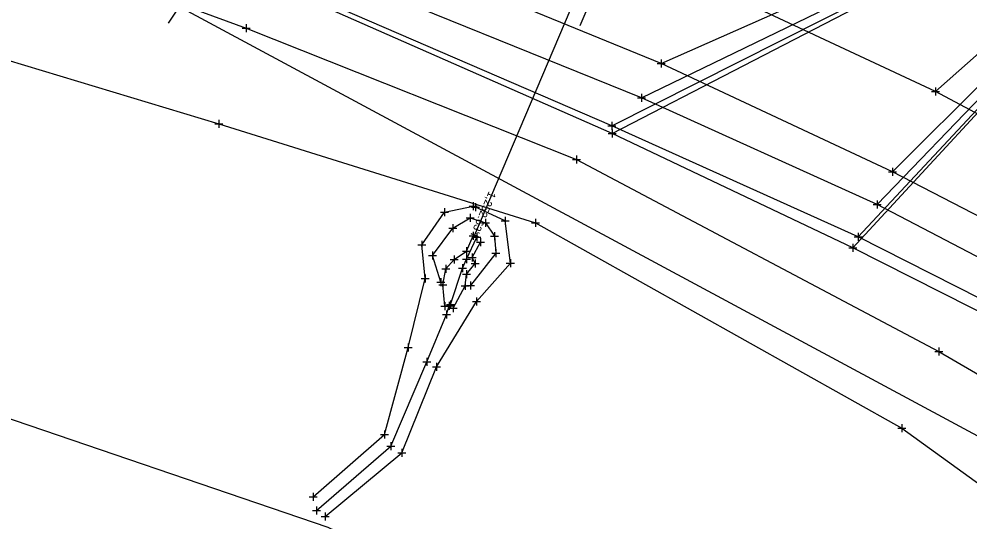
# Model space of a CAD drawing. Extents: x 125846 to 128609, y 511011 to 513388.
# Drawn here: x 126111.9 to 126230.6, y 513200.2 to 513263 of the extents above; entities that cross this region are included whole.
import ezdxf

# ---------------------------------------------------------------- set-up
doc = ezdxf.new("R2010")
doc.units = 0
for name, color, linetype in [('DR_X_Ditch', 7, 'Continuous'), ('DR_X_Elev_Flow', 7, 'Continuous'), ('DR_X_Storm_Sewer', 7, 'Continuous'), ('DR_X_Text', 7, 'Continuous'), ('DT_X_Terrain_Boundary', 7, 'Continuous'), ('PM_X_CL_Double_Solid', 7, 'Continuous'), ('PM_X_Edge_Line', 7, 'Continuous'), ('PV_X_COP', 7, 'Continuous'), ('PV_X_EOP', 7, 'Continuous'), ('PV_X_Shoulder_Aggregate', 7, 'Continuous'), ('RD_X_GR_Lt', 7, 'Continuous'), ('SC_Scratch1', 7, 'Continuous'), ('SV_Observation', 7, 'Continuous'), ('SV_X_Break_Lines', 7, 'Continuous'), ('UT_X_Overhead_Cable_TV', 7, 'Continuous'), ('UT_X_Overhead_Electric', 7, 'Continuous'), ('UT_X_Sanitary_Line', 7, 'Continuous')]:
    doc.layers.add(name, color=color, linetype=linetype)

msp = doc.modelspace()

# ---------------------------------------------------------------- linework, layer by layer
at = {"layer": 'DR_X_Ditch'}
for points in [[(126165.09, 513227.16), (126164.81, 513229.85), (126165.19, 513231.85), (126166.23, 513232.99), (126167.78, 513234.05), (126168.63, 513235.94)], [(126166.1, 513226.94), (126167.6, 513229.72), (126167.77, 513231.18), (126168.86, 513232.49), (126168.51, 513233.26), (126169.52, 513235.18)], [(126149.02, 513201.65), (126158.34, 513209.69), (126162.81, 513220.23), (126165.29, 513226.13), (126165.6, 513227.21)]]:
    msp.add_lwpolyline(points, dxfattribs=at)
at = {"layer": 'DR_X_Elev_Flow'}
for p, q in [((126168.32, 513236.26), (126169.25, 513235.87)), ((126168.98, 513236.53), (126168.59, 513235.6)), ((126168.79, 513236.06), (126168.79, 513236.06))]:
    msp.add_line(p, q, dxfattribs=at)
at = {"layer": 'DR_X_Storm_Sewer'}
msp.add_line((126200.85, 513311.44), (126168.79, 513236.06), dxfattribs=at)
at = {"layer": 'DR_X_Text'}
msp.add_line((126181.97, 513262.21), (126189.59, 513280.13), dxfattribs=at)
at = {"layer": 'DT_X_Terrain_Boundary'}
msp.add_line((126133.91, 513267.69), (126130.49, 513262.51), dxfattribs=at)
at = {"layer": 'PM_X_CL_Double_Solid'}
msp.add_lwpolyline([(126636.02, 512759.4), (126615.05, 512794.2), (126593.25, 512831.82), (126573.13, 512865.78), (126548.62, 512907.97), (126527.48, 512943.53), (126502.23, 512985.51), (126481.23, 513018.85), (126459.49, 513051.36), (126435.34, 513083.61), (126410.1, 513114.17), (126382.09, 513143.77), (126354.34, 513170.58), (126324.59, 513194.52), (126296.41, 513214.57), (126261.19, 513235.43), (126226.4, 513253.99), (126196.16, 513268.13), (126155.65, 513284.48), (126122.95, 513296.87), (126084.02, 513309.98), (126040.97, 513324.81)], dxfattribs=at)
at = {"layer": 'PM_X_Edge_Line'}
msp.add_lwpolyline([(126641.9, 512726.19), (126625.34, 512754.34), (126605.08, 512788.94), (126583.36, 512826.69), (126563.04, 512860.47), (126538.92, 512902.03), (126518.32, 512936.12), (126492.37, 512979.06), (126471.35, 513012.5), (126449.88, 513044.72), (126425.49, 513077.8), (126401.14, 513107.45), (126374.19, 513136.08), (126346.62, 513162.23), (126316.54, 513186.44), (126289.7, 513205.32), (126254.95, 513226.42), (126221.02, 513243.96), (126192.1, 513257.47), (126151.32, 513274.16), (126119.39, 513285.85), (126084.84, 513297.83), (126036.98, 513314.19)], dxfattribs=at)
at = {"layer": 'PV_X_COP'}
msp.add_lwpolyline([(126636.02, 512759.4), (126615.05, 512794.2), (126593.25, 512831.82), (126573.13, 512865.78), (126548.62, 512907.97), (126527.48, 512943.53), (126502.23, 512985.51), (126481.23, 513018.85), (126459.49, 513051.36), (126435.34, 513083.61), (126410.1, 513114.17), (126382.09, 513143.77), (126354.34, 513170.58), (126324.59, 513194.52), (126296.41, 513214.57), (126261.19, 513235.43), (126226.4, 513253.99), (126196.16, 513268.13), (126155.65, 513284.48), (126122.95, 513296.87), (126084.02, 513309.98), (126040.97, 513324.81)], dxfattribs=at)
at = {"layer": 'PV_X_EOP'}
msp.add_lwpolyline([(126637.98, 512724.06), (126621.53, 512752.01), (126602.03, 512784.44), (126578.51, 512824.31), (126558.07, 512859.52), (126534.26, 512899.49), (126514.02, 512933.73), (126488.13, 512977.21), (126467.93, 513009.24), (126445.31, 513042.52), (126421.52, 513074.55), (126397.03, 513104.15), (126370.98, 513132.02), (126342.57, 513158.56), (126313.71, 513182.07), (126286.69, 513201.08), (126252.27, 513222.55), (126219.11, 513239.86), (126189.65, 513253.2), (126149.87, 513269.3), (126117, 513281.26), (126083.11, 513293.41), (126035.31, 513309.49)], dxfattribs=at)
at = {"layer": 'PV_X_Shoulder_Aggregate'}
msp.add_lwpolyline([(126633.73, 512721.34), (126617.93, 512747.83), (126597.86, 512781.29), (126573.04, 512822.36), (126553.24, 512856.32), (126529.12, 512897.19), (126509.18, 512930.83), (126483.18, 512974.01), (126464.03, 513005.56), (126440.77, 513039.49), (126417.25, 513071.53), (126392.91, 513100.9), (126367.39, 513127.29), (126339.96, 513154.19), (126309.91, 513178.35), (126284.4, 513196.29), (126249.43, 513217.59), (126216.07, 513234.45), (126185.97, 513248.75), (126148.5, 513265.21), (126114.74, 513277.88), (126082.21, 513289.55), (126033.87, 513305.23)], dxfattribs=at)
at = {"layer": 'RD_X_GR_Lt'}
msp.add_lwpolyline([(126634.88, 512722.09), (126619.21, 512748.78), (126598.9, 512782.21), (126574.93, 512822.94), (126554.61, 512857.11), (126530.54, 512897.76), (126510.25, 512931.79), (126484.51, 512975.03), (126464.6, 513006.58), (126442.12, 513040.34), (126418.42, 513072.38), (126393.86, 513101.97), (126367.84, 513128.84), (126340.29, 513155.37), (126310.98, 513178.92), (126284.67, 513197.83), (126250.35, 513218.8), (126216.71, 513235.84), (126185.96, 513249.69), (126148.63, 513265.85), (126115.89, 513278.62), (126082.39, 513290.6), (126034.53, 513306.5)], dxfattribs=at)
at = {"layer": 'SV_Observation'}
for p in [(126185.96, 513249.69), (126185.97, 513248.75), (126189.65, 513253.2), (126192.1, 513257.47), (126216.07, 513234.45), (126216.71, 513235.84), (126219.11, 513239.86), (126221.02, 513243.96), (126226.4, 513253.99), (126226.4, 513253.99)]:
    msp.add_line(p, (126268.6, 513291.36), dxfattribs=at)
at = {"layer": 'SV_X_Break_Lines'}
for points in [[(125946.44, 513329.01), (126006.88, 513306.37), (126050.24, 513295.42), (126104.19, 513275.13), (126140.27, 513261.88), (126181.51, 513245.48), (126226.81, 513221.51), (126268.34, 513197.39), (126318.54, 513162.11), (126344.35, 513136.62), (126353.66, 513127.02)], [(125947.37, 513316.82), (126001.11, 513295.8), (126045.04, 513284.34), (126099.25, 513261.26), (126136.85, 513249.95), (126176.42, 513237.57), (126222.16, 513211.96), (126260.77, 513184.08), (126309.68, 513145.05), (126320.88, 513131.94), (126329.73, 513119.29)], [(126929.12, 511999.3), (126903.84, 512110.39), (126871.86, 512233.61), (126833.09, 512269.75), (126730.01, 512369.5), (126679.2, 512443.95), (126610.71, 512557), (126575.33, 512586.13), (126534.96, 512653.66), (126509.99, 512711.61), (126473.57, 512790.72), (126439.57, 512852.97), (126379.8, 512929.28), (126333.79, 513016.36), (126275.48, 513095.64), (126210.09, 513171.16), (126150.48, 513199.56), (126106, 513214.69), (126034.78, 513236.32), (125916.78, 513276.5), (125860.26, 513285.89)], [(126148.63, 513203.37), (126157.54, 513211.15), (126160.48, 513222), (126162.63, 513230.65), (126162.21, 513234.82), (126165.05, 513238.93), (126168.63, 513239.65)], [(126150.14, 513200.91), (126159.72, 513208.87), (126164.04, 513219.6), (126169.03, 513227.77), (126173.26, 513232.54), (126172.6, 513237.84), (126168.91, 513239.52)], [(126164.57, 513230.17), (126163.55, 513233.52), (126166.08, 513236.91), (126168.25, 513238.2), (126170.15, 513237.59), (126171.27, 513235.9), (126171.46, 513233.8), (126168.29, 513229.74)], [(126165.79, 513227.4), (126167.27, 513231.93), (126167.77, 513233.04), (126169.07, 513235.79)]]:
    msp.add_lwpolyline(points, dxfattribs=at)
at = {"layer": 'UT_X_Overhead_Cable_TV'}
msp.add_lwpolyline([(127118.02, 511376.72), (127063.55, 511579.79), (127023.04, 511824.95), (126985.21, 512054.96), (126933.25, 512195.56), (126884.63, 512286.17), (126796.71, 512439.39), (126673.51, 512645.42), (126573.76, 512808.4), (126463.86, 512978.44), (126309.69, 513169.01), (126131.86, 513264.58), (125938.03, 513331.21)], dxfattribs=at)
at = {"layer": 'UT_X_Overhead_Electric'}
msp.add_lwpolyline([(127118.02, 511376.72), (127063.55, 511579.79), (127023.04, 511824.95), (126985.21, 512054.96), (126933.25, 512195.56), (126884.63, 512286.17), (126796.71, 512439.39), (126673.51, 512645.42), (126573.76, 512808.4), (126463.86, 512978.44), (126309.69, 513169.01), (126131.86, 513264.58), (125938.03, 513331.21)], dxfattribs=at)
at = {"layer": 'UT_X_Sanitary_Line'}
for p, q in [((126139.77, 513261.88), (126140.77, 513261.88)), ((126140.27, 513262.38), (126140.27, 513261.38)), ((126140.27, 513261.88), (126140.27, 513261.88)), ((126191.6, 513257.47), (126192.6, 513257.47)), ((126192.1, 513257.97), (126192.1, 513256.97)), ((126192.1, 513257.47), (126192.1, 513257.47)), ((126189.65, 513253.7), (126189.65, 513252.7)), ((126225.9, 513253.99), (126226.9, 513253.99)), ((126225.9, 513253.99), (126226.9, 513253.99)), ((126226.4, 513254.49), (126226.4, 513253.49)), ((126226.4, 513254.49), (126226.4, 513253.49)), ((126226.4, 513253.99), (126226.4, 513253.99)), ((126226.4, 513253.99), (126226.4, 513253.99)), ((126189.15, 513253.2), (126190.15, 513253.2)), ((126189.65, 513253.2), (126189.65, 513253.2)), ((126136.35, 513249.95), (126137.35, 513249.95)), ((126136.85, 513250.45), (126136.85, 513249.45)), ((126136.85, 513249.95), (126136.85, 513249.95)), ((126185.96, 513250.19), (126185.96, 513249.19)), ((126185.46, 513249.69), (126186.46, 513249.69)), ((126185.47, 513248.75), (126186.47, 513248.75)), ((126185.96, 513249.69), (126185.96, 513249.69)), ((126185.97, 513249.25), (126185.97, 513248.25)), ((126185.97, 513248.75), (126185.97, 513248.75)), ((126181.01, 513245.48), (126182.01, 513245.48)), ((126181.51, 513245.98), (126181.51, 513244.98)), ((126181.51, 513245.48), (126181.51, 513245.48)), ((126221.02, 513244.46), (126221.02, 513243.46)), ((126220.52, 513243.96), (126221.52, 513243.96)), ((126221.02, 513243.96), (126221.02, 513243.96)), ((126165.05, 513239.43), (126165.05, 513238.43)), ((126168.13, 513239.65), (126169.13, 513239.65)), ((126168.41, 513239.52), (126169.41, 513239.52)), ((126168.63, 513240.15), (126168.63, 513239.15)), ((126168.63, 513239.65), (126168.63, 513239.65)), ((126168.91, 513240.02), (126168.91, 513239.02)), ((126168.91, 513239.52), (126168.91, 513239.52)), ((126218.61, 513239.86), (126219.61, 513239.86)), ((126219.11, 513240.36), (126219.11, 513239.36)), ((126219.11, 513239.86), (126219.11, 513239.86)), ((126164.55, 513238.93), (126165.55, 513238.93)), ((126165.05, 513238.93), (126165.05, 513238.93)), ((126167.75, 513238.2), (126168.75, 513238.2)), ((126168.25, 513238.7), (126168.25, 513237.7)), ((126168.25, 513238.2), (126168.25, 513238.2)), ((126170.15, 513238.09), (126170.15, 513237.09)), ((126172.6, 513238.34), (126172.6, 513237.34)), ((126176.42, 513238.07), (126176.42, 513237.07)), ((126165.58, 513236.91), (126166.58, 513236.91)), ((126166.08, 513237.41), (126166.08, 513236.41)), ((126166.08, 513236.91), (126166.08, 513236.91)), ((126169.65, 513237.59), (126170.65, 513237.59)), ((126170.15, 513237.59), (126170.15, 513237.59)), ((126172.1, 513237.84), (126173.1, 513237.84)), ((126172.6, 513237.84), (126172.6, 513237.84)), ((126175.92, 513237.57), (126176.92, 513237.57)), ((126176.42, 513237.57), (126176.42, 513237.57)), ((126168.13, 513235.94), (126169.13, 513235.94)), ((126168.57, 513235.79), (126169.57, 513235.79)), ((126168.63, 513236.44), (126168.63, 513235.44)), ((126168.63, 513235.94), (126168.63, 513235.94)), ((126169.07, 513236.29), (126169.07, 513235.29)), ((126169.07, 513235.79), (126169.07, 513235.79)), ((126169.52, 513235.68), (126169.52, 513234.68)), ((126170.77, 513235.9), (126171.77, 513235.9)), ((126171.27, 513236.4), (126171.27, 513235.4)), ((126171.27, 513235.9), (126171.27, 513235.9)), ((126216.21, 513235.84), (126217.21, 513235.84)), ((126216.71, 513236.34), (126216.71, 513235.34)), ((126216.71, 513235.84), (126216.71, 513235.84)), ((126161.71, 513234.82), (126162.71, 513234.82)), ((126162.21, 513235.32), (126162.21, 513234.32)), ((126162.21, 513234.82), (126162.21, 513234.82)), ((126167.78, 513234.55), (126167.78, 513233.55)), ((126169.02, 513235.18), (126170.02, 513235.18)), ((126169.52, 513235.18), (126169.52, 513235.18)), ((126216.07, 513234.95), (126216.07, 513233.95)), ((126163.05, 513233.52), (126164.05, 513233.52)), ((126163.55, 513234.02), (126163.55, 513233.02)), ((126163.55, 513233.52), (126163.55, 513233.52)), ((126166.23, 513233.49), (126166.23, 513232.49)), ((126167.28, 513234.05), (126168.28, 513234.05)), ((126167.77, 513233.54), (126167.77, 513232.54)), ((126167.78, 513234.05), (126167.78, 513234.05)), ((126168.51, 513233.76), (126168.51, 513232.76)), ((126170.96, 513233.8), (126171.96, 513233.8)), ((126171.46, 513234.3), (126171.46, 513233.3)), ((126171.46, 513233.8), (126171.46, 513233.8)), ((126215.57, 513234.45), (126216.57, 513234.45)), ((126216.07, 513234.45), (126216.07, 513234.45)), ((126165.19, 513232.35), (126165.19, 513231.35)), ((126165.73, 513232.99), (126166.73, 513232.99)), ((126166.23, 513232.99), (126166.23, 513232.99)), ((126167.27, 513233.04), (126168.27, 513233.04)), ((126167.27, 513232.43), (126167.27, 513231.43)), ((126167.77, 513233.04), (126167.77, 513233.04)), ((126168.01, 513233.26), (126169.01, 513233.26)), ((126168.36, 513232.49), (126169.36, 513232.49)), ((126168.51, 513233.26), (126168.51, 513233.26)), ((126168.86, 513232.99), (126168.86, 513231.99)), ((126168.86, 513232.49), (126168.86, 513232.49)), ((126172.76, 513232.54), (126173.76, 513232.54)), ((126173.26, 513233.04), (126173.26, 513232.04)), ((126173.26, 513232.54), (126173.26, 513232.54)), ((126162.63, 513231.15), (126162.63, 513230.15)), ((126164.69, 513231.85), (126165.69, 513231.85)), ((126165.19, 513231.85), (126165.19, 513231.85)), ((126166.77, 513231.93), (126167.77, 513231.93)), ((126167.27, 513231.93), (126167.27, 513231.93)), ((126167.27, 513231.18), (126168.27, 513231.18)), ((126167.77, 513231.68), (126167.77, 513230.68)), ((126167.77, 513231.18), (126167.77, 513231.18)), ((126162.13, 513230.65), (126163.13, 513230.65)), ((126162.63, 513230.65), (126162.63, 513230.65)), ((126164.07, 513230.17), (126165.07, 513230.17)), ((126164.31, 513229.85), (126165.31, 513229.85)), ((126164.57, 513230.67), (126164.57, 513229.67)), ((126164.57, 513230.17), (126164.57, 513230.17)), ((126164.81, 513230.35), (126164.81, 513229.35)), ((126164.81, 513229.85), (126164.81, 513229.85)), ((126167.6, 513230.22), (126167.6, 513229.22)), ((126167.79, 513229.74), (126168.79, 513229.74)), ((126168.29, 513230.24), (126168.29, 513229.24)), ((126168.29, 513229.74), (126168.29, 513229.74)), ((126167.1, 513229.72), (126168.1, 513229.72)), ((126167.6, 513229.72), (126167.6, 513229.72)), ((126165.09, 513227.66), (126165.09, 513226.66)), ((126165.29, 513227.4), (126166.29, 513227.4)), ((126165.6, 513227.71), (126165.6, 513226.71)), ((126165.79, 513227.9), (126165.79, 513226.9)), ((126165.79, 513227.4), (126165.79, 513227.4)), ((126166.1, 513227.44), (126166.1, 513226.44)), ((126168.53, 513227.77), (126169.53, 513227.77)), ((126169.03, 513228.27), (126169.03, 513227.27)), ((126169.03, 513227.77), (126169.03, 513227.77)), ((126164.59, 513227.16), (126165.59, 513227.16)), ((126165.09, 513227.16), (126165.09, 513227.16)), ((126165.1, 513227.21), (126166.1, 513227.21)), ((126165.29, 513226.63), (126165.29, 513225.63)), ((126165.6, 513227.21), (126165.6, 513227.21)), ((126165.6, 513226.94), (126166.6, 513226.94)), ((126166.1, 513226.94), (126166.1, 513226.94)), ((126164.79, 513226.13), (126165.79, 513226.13)), ((126165.29, 513226.13), (126165.29, 513226.13)), ((126159.98, 513222), (126160.98, 513222)), ((126160.48, 513222.5), (126160.48, 513221.5)), ((126160.48, 513222), (126160.48, 513222)), ((126226.31, 513221.51), (126227.31, 513221.51)), ((126226.81, 513222.01), (126226.81, 513221.01)), ((126226.81, 513221.51), (126226.81, 513221.51)), ((126162.81, 513220.73), (126162.81, 513219.73)), ((126162.31, 513220.23), (126163.31, 513220.23)), ((126162.81, 513220.23), (126162.81, 513220.23)), ((126163.54, 513219.6), (126164.54, 513219.6)), ((126164.04, 513220.1), (126164.04, 513219.1)), ((126164.04, 513219.6), (126164.04, 513219.6)), ((126221.66, 513211.96), (126222.66, 513211.96)), ((126222.16, 513212.46), (126222.16, 513211.46)), ((126222.16, 513211.96), (126222.16, 513211.96)), ((126157.04, 513211.15), (126158.04, 513211.15)), ((126157.54, 513211.65), (126157.54, 513210.65)), ((126157.54, 513211.15), (126157.54, 513211.15)), ((126157.84, 513209.69), (126158.84, 513209.69)), ((126158.34, 513210.19), (126158.34, 513209.19)), ((126158.34, 513209.69), (126158.34, 513209.69)), ((126159.22, 513208.87), (126160.22, 513208.87)), ((126159.72, 513209.37), (126159.72, 513208.37)), ((126159.72, 513208.87), (126159.72, 513208.87)), ((126148.63, 513203.87), (126148.63, 513202.87)), ((126148.13, 513203.37), (126149.13, 513203.37)), ((126148.63, 513203.37), (126148.63, 513203.37)), ((126148.52, 513201.65), (126149.52, 513201.65)), ((126149.02, 513202.15), (126149.02, 513201.15)), ((126149.02, 513201.65), (126149.02, 513201.65)), ((126150.14, 513201.41), (126150.14, 513200.41)), ((126149.64, 513200.91), (126150.64, 513200.91)), ((126150.14, 513200.91), (126150.14, 513200.91))]:
    msp.add_line(p, q, dxfattribs=at)

# ---------------------------------------------------------------- texts
at = {"layer": 'SC_Scratch1'}
msp.add_text("1,252.63'", height=1, rotation=246.9559, dxfattribs=at).set_placement((126170.59, 513241.58))

doc.saveas('drawing.dxf')
